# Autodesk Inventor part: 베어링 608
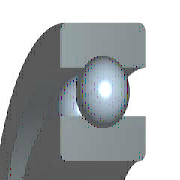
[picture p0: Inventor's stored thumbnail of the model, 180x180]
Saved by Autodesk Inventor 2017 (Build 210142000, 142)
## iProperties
IsCustomPart: 1
Created: 2012-02
Part Number: 베어링 608
Material: 강철, 연강
Description: 깊은 그루브 볼 베어링
Document SubType Name: Modeling
Standard: KS B 2023
Designer: mduedu
Standards Organization: KS
Language: ko-KR
Size Designation: 608 - 8 x 22 x 7
Categories: <MemberInstance><Categories><Category DisplayName="샤프트 부품" InternalName="7f7aeb1f-a693-4053-b835-cee3144e0d98" Mnemonic="SHFT"><Category DisplayName="베어링" Inter
Density: 7.85 g/cm^3
Appearance: 노란색
Mass: 12.145 g
Surface Area: 20.0754 cm^2
Volume: 1.54714 cm^3
Author: mduedu
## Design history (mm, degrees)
sketch "스케치" dims "d0" = 3.64 (= -0.26 x WD + 0.26 x BD)
  geometry: L1 (1.68, 7.5)-(5.32, 7.5); L2 (3.5, 7.5)-(3.5, 5.68); L3 (3.5, 7.5)-(3.5, 9.32); L4 (2.148, 6.282)-(0, 6.282); L5 (0, 4)-(7, 4); L6 (2.148, 8.718)-(0, 8.718); L7 (0, 11)-(7, 11); L8 (7, 4)-(7, 6.282); L9 (4.852, 6.282)-(7, 6.282); L10 (4.852, 8.718)-(7, 8.718); L11 (7, 11)-(7, 8.718); L12 (-1.4, 0)-(8.4, 0) reference; L13 (0, -0.3)-(0, 5.3) reference
  constraints: 22 end point, 4 point on line, 2 collinear, 2 perpendicular, 2 symmetric about line, 1 midpoint, 1 parallel, 14 other
  dimensions: "d9" = 8 diameter of L5 L12 (= WD); "d11" = 22 diameter of L7 L12 (= BD); "d12" = 7 distance between parallel lines of L8 L13 (= KB); "d13" = 12.564 diameter of L9 L12 (= 0.326 x BD + 0.674 x WD)
revolve "본체" stored, may be unused: angle "d6" = 90 deg
revolve "볼" stored, may be unused: angle "d7" = 90 deg
pattern_circular "IDS_ARRAYBALL[SIMPL:T]" dims angle "d3" = 360 deg
body "Solid1"
fillet "모깎기1" dims "d1" = 0.3 (= KRS)
other parameters: "WD" = 8 [user parameter; used in 5 equation terms], "BD" = 22 [user parameter; used in 5 equation terms], "KB" = 7 [user parameter; used in 1 equation term], "KRS" = 0.3 [user parameter; used in 1 equation term], "d4" = 0, "d5" = 0, "d8" = 0, "d14" = 0, "d15" = 0, "BBA" = 0 [user parameter], "BC0" = 1370000 [user parameter], "BC" = 3250000 [user parameter], "BR" = 11 (= 0.5 x BD) [user parameter], "WR" = 4 (= 0.5 x WD) [user parameter]
